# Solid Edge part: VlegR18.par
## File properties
Author: Türk
Template: Iso Part.par
Last saved by: Türk
Revision: 15
Application: Solid Edge
Accuracy: 0,990
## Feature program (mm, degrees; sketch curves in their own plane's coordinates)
pattern "PatternOccurrence_1"  XOffset = 45 deg
pattern "PatternOccurrence_2"  XCount = 5; XOffset = 72 deg
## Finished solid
Body 1: sheet body, 4 faces, 83 edges, 83 vertices.
  Faces by surface: plane 4
  Edges by curve: line 55, circle 18, spline 10
Body 2: solid body, 140 faces, 339 edges, 182 vertices, 2 internal voids.
  Faces by surface: cylinder 65, plane 24, torus 23, blend 14, cone 9, spun 5
  Edges by curve: intersection 145, circle 130, line 64
Bounding box of the edges (mm; curved faces can reach further): 235.000 x 457.200 x 457.200, from (-125, -228.6, -228.6) to (110, 228.6, 228.6).
Cylindrical faces by radius (mm): R4 x16, R6 x5, R15 x5, R25 x16, R62.5 x1, R80 x8, R174.2298 x8, R203.6 x2, R216.1 x2, R228.6 x2
Conical faces (half-angle, radius in mm at the cone's reference point): 2.0106 deg R178.4522 x2, 5.4632 deg R201.6202 x2, 54.824 deg R174.2298 x1, 54.824 deg R203.0605 x2, 54.824 deg R203.6 x1, 83.4677 deg R62.5 x1
Toroidal faces (ring radius, tube radius in mm): R79 r1 x7, R136.945 r40 x8, R205.6 r2 x2, R214.1 r2 x2, R226.6 r2 x4
Planar faces by outward normal: +x 4, -x 4, oblique 16
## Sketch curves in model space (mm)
line (-30, -64.8293, 161.7195) -> (-30, -65.6784, 163.1901)
line (69.3, 0, 174.2298) -> (64.3, 0, 174.2298)
line (-30, 0, 62.5) -> (-35, 0, 62.5)
line (98, 0, 203.6) -> (18.9114, 0, 237.8791)
line (-98, 0, 203.6) -> (-98, 0, 288.5518)
line (-98, 0, 203.6) -> (-18.9114, 0, 237.8791)
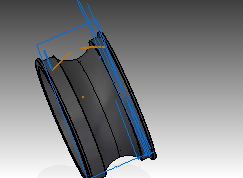
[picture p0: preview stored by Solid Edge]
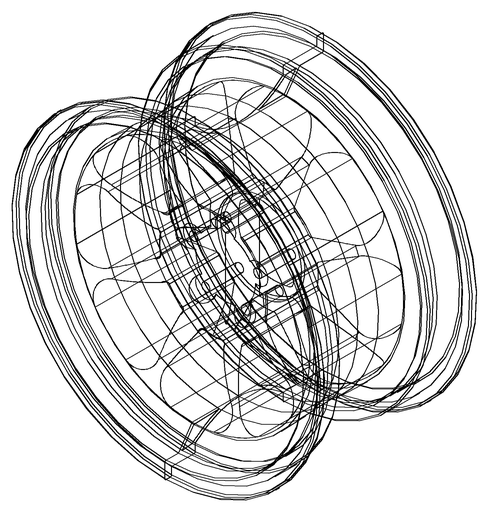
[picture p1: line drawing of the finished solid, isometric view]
